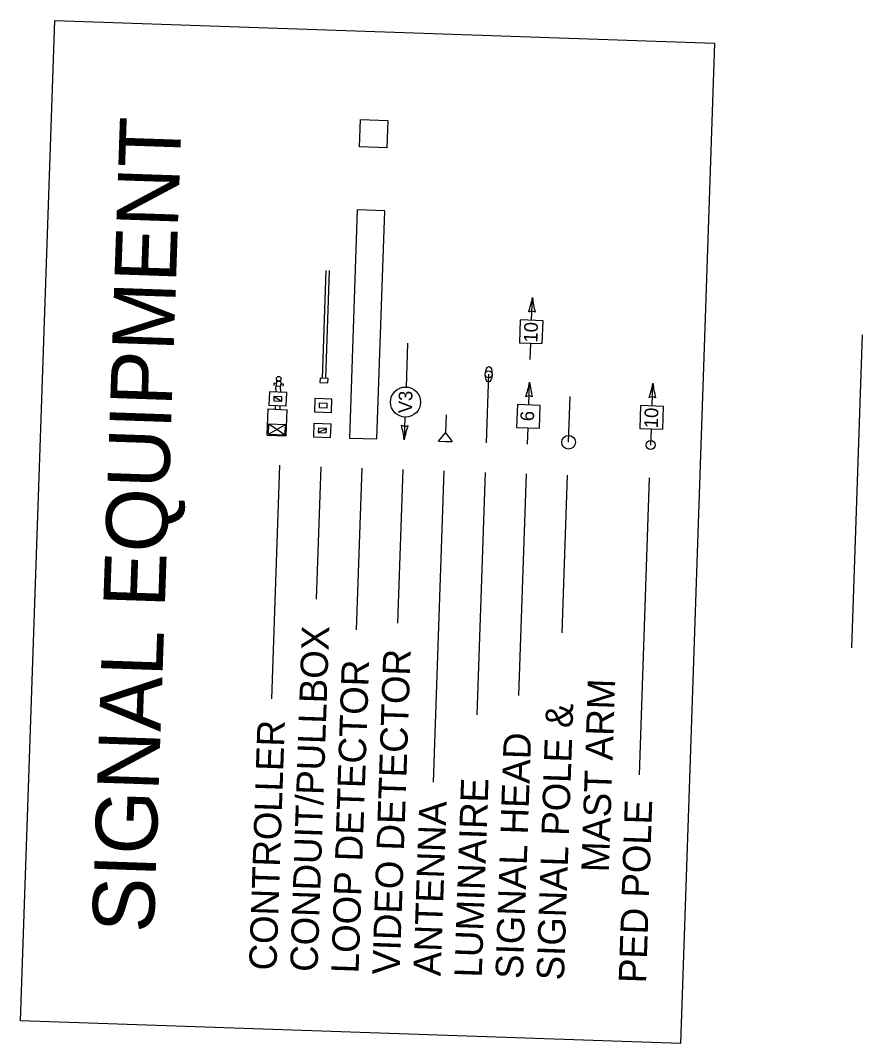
# Model space of a CAD drawing. Extents: x 981632 to 1295361, y 220574 to 1844132.
# Drawn here: x 993005.6 to 993190, y 1843907.8 to 1844131.8 of the extents above; entities that cross this region are included whole.
import ezdxf

# ---------------------------------------------------------------- set-up
doc = ezdxf.new("R2010")
doc.units = 0
for name, color, linetype in [('Default', 7, 'Continuous'), ('No Plot', 7, 'Continuous'), ('V-SIGNAL-CONDUIT', 7, 'Continuous'), ('V-SIGNAL-CONTROLLER', 7, 'Continuous'), ('V-SIGNAL-HEAD', 7, 'Continuous'), ('V-SIGNAL-LOOP', 7, 'Continuous'), ('V-SIGNAL-MAST', 7, 'Continuous'), ('V-SIGNAL-POLE', 7, 'Continuous')]:
    doc.layers.add(name, color=color, linetype=linetype)

msp = doc.modelspace()

# ---------------------------------------------------------------- linework, layer by layer
at = {"layer": 'Default'}
for p, q in [((993060.65, 1843983.26), (993062.4, 1844034.39)), ((993070.41, 1844005.08), (993071.4, 1844034.08)), ((993079.18, 1843998.35), (993080.39, 1844033.77)), ((993088.24, 1843999.82), (993089.39, 1844033.46)), ((993096.05, 1843964.98), (993098.38, 1844033.15)), ((993105.56, 1843979.72), (993107.38, 1844032.84)), ((993114.71, 1843983.98), (993116.37, 1844032.54)), ((993124.18, 1843997.7), (993125.37, 1844032.23)), ((993141.13, 1843966.59), (993143.36, 1844031.61))]:
    msp.add_line(p, q, dxfattribs=at)
at = {"layer": 'No Plot'}
msp.add_line((993187.63, 1843994.4), (993189.98, 1844062.92), dxfattribs=at)
at = {"layer": 'V-SIGNAL-CONDUIT'}
for p, q in [((993071.69, 1844053.42), (993072.5, 1844077.06)), ((993072.43, 1844053.39), (993073.24, 1844077.03)), ((993061.09, 1844052.34), (993061.06, 1844051.84)), ((993061.59, 1844052.31), (993061.09, 1844052.34)), ((993061.62, 1844052.8), (993061.56, 1844051.81)), ((993061.62, 1844052.8), (993062.62, 1844052.73)), ((993062.62, 1844052.73), (993062.55, 1844051.74)), ((993062.59, 1844052.24), (993063.09, 1844052.2)), ((993063.09, 1844052.2), (993063.05, 1844051.7)), ((993071.19, 1844053.43), (993071.16, 1844052.52)), ((993071.16, 1844052.52), (993072.91, 1844052.46)), ((993072.94, 1844053.37), (993071.19, 1844053.43)), ((993072.91, 1844052.46), (993072.94, 1844053.37)), ((993060.13, 1844050.47), (993059.99, 1844047.56)), ((993063.88, 1844050.3), (993060.13, 1844050.47)), ((993061.53, 1844051.11), (993061.56, 1844051.81)), ((993061.53, 1844051.11), (993061.53, 1844050.41)), ((993061.56, 1844051.81), (993062.55, 1844051.74)), ((993062.53, 1844051.08), (993062.55, 1844051.77)), ((993062.53, 1844051.08), (993062.53, 1844050.37)), ((993063.74, 1844047.38), (993063.88, 1844050.3)), ((993059.99, 1844047.56), (993063.74, 1844047.38)), ((993061.08, 1844049.43), (993061.04, 1844048.51)), ((993061.04, 1844048.51), (993062.79, 1844048.43)), ((993062.83, 1844049.34), (993061.08, 1844049.43)), ((993061.08, 1844049.43), (993062.79, 1844048.43)), ((993061.38, 1844047.49), (993061.38, 1844046.65)), ((993062.79, 1844048.43), (993062.83, 1844049.34)), ((993070.04, 1844049), (993069.94, 1844046.08)), ((993073.78, 1844048.87), (993070.04, 1844049)), ((993071, 1844047.96), (993070.97, 1844047.05)), ((993072.75, 1844047.9), (993071, 1844047.96)), ((993072.72, 1844046.99), (993072.75, 1844047.9)), ((993073.68, 1844045.95), (993073.78, 1844048.87)), ((993062.38, 1844047.45), (993062.38, 1844046.62)), ((993069.94, 1844046.08), (993073.68, 1844045.95)), ((993070.97, 1844047.05), (993072.72, 1844046.99)), ((993069.85, 1844043.53), (993069.75, 1844040.61)), ((993073.6, 1844043.4), (993069.85, 1844043.53)), ((993073.5, 1844040.48), (993073.6, 1844043.4)), ((993070.81, 1844042.49), (993070.78, 1844041.58)), ((993070.78, 1844041.58), (993072.56, 1844042.43)), ((993070.78, 1844041.58), (993072.53, 1844041.52)), ((993072.56, 1844042.43), (993070.81, 1844042.49)), ((993072.53, 1844041.52), (993072.56, 1844042.43)), ((993069.75, 1844040.61), (993073.5, 1844040.48))]:
    msp.add_line(p, q, dxfattribs=at)
msp.add_circle((993062.13, 1844053.33), 0.5, dxfattribs=at)
at = {"layer": 'V-SIGNAL-CONTROLLER'}
for p, q in [((993059.63, 1844040.96), (993059.83, 1844046.71)), ((993059.83, 1844046.71), (993063.99, 1844046.56)), ((993063.79, 1844040.82), (993063.99, 1844046.56)), ((993059.89, 1844041.2), (993059.96, 1844043.45)), ((993059.89, 1844041.2), (993063.63, 1844043.32)), ((993059.96, 1844043.45), (993063.63, 1844043.32)), ((993059.96, 1844043.45), (993063.55, 1844041.07)), ((993063.55, 1844041.07), (993063.63, 1844043.32)), ((993059.63, 1844040.96), (993063.79, 1844040.82)), ((993059.89, 1844041.2), (993063.55, 1844041.07))]:
    msp.add_line(p, q, dxfattribs=at)
msp.add_lwpolyline([(993005.57, 1843912.73), (993013.08, 1844131.78), (993157.59, 1844126.82), (993150.08, 1843907.78)], close=True, dxfattribs=at)
at = {"layer": 'V-SIGNAL-HEAD'}
for p, q in [((993117.52, 1844066.13), (993117.69, 1844071.12)), ((993090.34, 1844061.12), (993090.01, 1844051.52)), ((993117.23, 1844057.56), (993117.35, 1844061.13)), ((993107.6, 1844039.31), (993108.11, 1844054.3)), ((993116.89, 1844047.57), (993117.06, 1844052.57)), ((993143.89, 1844047.37), (993144.07, 1844052.37)), ((993098.8, 1844045.42), (993098.67, 1844041.48)), ((993089.78, 1844044.92), (993089.61, 1844039.93)), ((993116.6, 1844039.01), (993116.72, 1844042.57)), ((993143.6, 1844038.81), (993143.73, 1844042.37)), ((993097.11, 1844039.67), (993098.61, 1844039.62)), ((993098.61, 1844039.62), (993100.1, 1844039.57))]:
    msp.add_line(p, q, dxfattribs=at)
for points in [[(993114.85, 1844061.22), (993119.85, 1844061.05), (993120.02, 1844066.04), (993115.02, 1844066.21)], [(993114.22, 1844042.66), (993119.22, 1844042.49), (993119.39, 1844047.49), (993114.39, 1844047.66)], [(993141.23, 1844042.46), (993146.23, 1844042.29), (993146.39, 1844047.29), (993141.39, 1844047.46)]]:
    msp.add_lwpolyline(points, close=True, dxfattribs=at)
msp.add_lwpolyline([(993097.11, 1844039.67), (993098.67, 1844041.48), (993100.1, 1844039.57)], dxfattribs=at)
for centre, radius in [((993108.12, 1844054.3), 0.75), ((993089.9, 1844048.22), 3.3)]:
    msp.add_circle(centre, radius, dxfattribs=at)
for centre, radius, start, end in [((993093.81, 1844075.57), 24.29, 341.7116, 349.4497), ((993141.82, 1844073.94), 24.29, 186.6664, 194.4045), ((993117.55, 1844066.78), 1.34, 56.2107, 119.9054), ((993093.18, 1844057.01), 24.29, 341.7116, 349.4497), ((993141.19, 1844055.39), 24.29, 186.6664, 194.4045), ((993120.18, 1844056.81), 24.29, 341.7116, 349.4497), ((993168.19, 1844055.19), 24.29, 186.6664, 194.4045), ((993116.91, 1844048.23), 1.34, 56.2107, 119.9054), ((993143.92, 1844048.03), 1.34, 56.2107, 119.9054), ((993089.76, 1844044.27), 1.34, 236.1974, 299.892), ((993065.48, 1844037.12), 24.29, 6.653, 14.3911), ((993113.49, 1844035.48), 24.29, 161.6982, 169.4364)]:
    msp.add_arc(centre, radius, start, end, dxfattribs=at)
msp.add_ellipse((993108.12, 1844054.3), major_axis=(-0.06, -1.7), ratio=0.441176, dxfattribs=at)
at = {"layer": 'V-SIGNAL-LOOP'}
for points in [[(993086.01, 1844109.9), (993085.8, 1844103.91), (993079.8, 1844104.11), (993080.01, 1844110.11)], [(993085.33, 1844090.11), (993079.33, 1844090.31), (993077.62, 1844040.34), (993083.61, 1844040.14)]]:
    msp.add_lwpolyline(points, close=True, dxfattribs=at)
at = {"layer": 'V-SIGNAL-POLE'}
msp.add_line((993125.61, 1844039.42), (993125.96, 1844049.47), dxfattribs=at)
for centre, radius in [((993125.61, 1844039.42), 1.5), ((993143.6, 1844038.81), 1)]:
    msp.add_circle(centre, radius, dxfattribs=at)

# ---------------------------------------------------------------- texts
at = {"layer": 'Default'}
msp.add_text('SIGNAL EQUIPMENT', height=13.5, rotation=88.0361, dxfattribs=at).set_placement((993034.74, 1843931.89))
at = {"layer": 'V-SIGNAL-HEAD'}
for s, rotation, p in [('10', 88.0961, (993118.77, 1844061.23)), ('V3', 88.708, (993091.32, 1844045.76)), ('6', 88.1517, (993118.02, 1844044)), ('10', 88.0961, (993145.14, 1844042.48))]:
    msp.add_text(s, height=3, rotation=rotation, dxfattribs=at).set_placement(p)
at = {"layer": 'V-SIGNAL-MAST'}
for s, p in [('CONDUIT/PULLBOX', (993070.61, 1843923.39)), ('VIDEO DETECTOR', (993088.6, 1843922.77)), ('LOOP DETECTOR', (993079.6, 1843923.08)), ('MAST ARM', (993134.39, 1843945.22)), ('SIGNAL POLE &', (993124.57, 1843921.54)), ('CONTROLLER', (993061.61, 1843923.7)), ('SIGNAL HEAD', (993115.58, 1843921.85)), ('LUMINAIRE', (993106.58, 1843922.16)), ('ANTENNA', (993097.59, 1843922.47)), ('PED POLE', (993142.56, 1843920.92))]:
    msp.add_text(s, height=6, rotation=88.0361, dxfattribs=at).set_placement(p)

doc.saveas('drawing.dxf')
